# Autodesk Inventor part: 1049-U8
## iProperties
Created: 2007-03
Part Number: 1049-U8
Document SubType Name: Modeling
Designer: Andy Moles
Material: Steel
Density: 7.85 g/cm^3
Author: Andy Moles
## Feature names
1. Extrusion1
2. miter cut [Extrusion]
3. Extrusion3
4. Extrusion4
5. Extrusion5
